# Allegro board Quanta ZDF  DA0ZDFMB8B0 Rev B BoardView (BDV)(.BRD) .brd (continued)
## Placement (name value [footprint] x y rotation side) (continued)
R1108  *4.7K_5%_2  [R0201]  87.92 27.16 90 top
R1109  *4.7K_5%_2  [R0201]  78.11 36.92 0 top
R1110  *4.7K_5%_2  [R0201]  78.11 36.16 0 top
R1111  *4.7K_5%_2  [R0201]  91.25 26.78 0 top
R1112  *4.7K_5%_2  [R0201]  91.25 26.04 0 top
R1113  *4.7K_5%_2  [R0201]  95.2 36.92 180 top
R1114  *4.7K_5%_2  [R0201]  95.2 37.63 180 top
R1501  75K_1%_2  [R0201]  81.03 25.9 90 top
R1502  75K_1%_2  [R0201]  119.19 47.66 90 top
R2001  1_1%_2  [R0201]  105 33.21 90 top
R2204  200K_1%_2  [R0201]  111.29 41.47 180 bottom
R2205  12K_5%_2  [R0201]  106.41 30.33 90 top
R2206  12K_5%_2  [R0201]  105.01 30.18 270 top
R2301  *24K_1%_4  [R0402]  113.04 42.3 0 bottom
R2302  *330K_1%_4  [R0402]  113.5 43.98 0 bottom
R2303  39K_1%_4  [R0402]  111.67 44.11 180 bottom
R2304  *7.5K_1%_2  [R0201]  112.66 43.14 180 bottom
R3001  0_5%_2  [R0201]  52.35 15.04 180 bottom
R3002  *0_5%_2  [R0201]  52.69 14.19 270 bottom
R3003  0_5%_2  [R0201]  51.19 14.19 90 bottom
R3004  *0_5%_2  [R0201]  51.49 12.95 270 bottom
R3005  0_5%_2  [R0201]  52.21 12.95 270 bottom
R3006  *0_5%_2  [R0201]  51.95 14.19 270 bottom
R4001  60.4_1%_2  [R0201]  78.19 44.29 0 top
R4404  240_1%_4  [R0402]  80.53 59.14 270 top
R4405  240_1%_4  [R0402]  81.54 59.14 270 top
R4407  *240_1%_4  [R0402]  82.56 59.14 270 top
R6206  *470_1%_2  [R0201]  106.18 27.13 180 top
R6207  *470_1%_2  [R0201]  107.29 27.13 0 top
R6209  *1K_1%_4  [R0402]  103.33 28.36 0 bottom
R6210  *1.5K_1%_4  [R0402]  104.7 28.49 270 bottom
R6225  *0_5%_4  [R0402]  103.49 26.37 0 bottom
R7701  *Short_0201  [S0201]  142.35 30.23 270 top
R8001  *Short_0201  [S0201]  114.18 35.52 0 top
R8201  1.5K_1%_2  [R0201]  114.05 40.2 0 top
R9499  2.2K_1%_2  [R0201]  54.47 7.5 90 top
R9572  1K_1%_2  [R0201]  141.46 28.96 0 bottom
R90154  4.7K_1%_4  [R0402]  24.62 16.39 0 bottom
R90155  4.7K_1%_4  [R0402]  26.4 16.39 180 bottom
R90163  *Short_0402  [S0402]  107.44 56.4 90 bottom
R90164  *Short_0603  [S0603]  114.2 50.13 180 top
R90264  *Short_0201  [S0201]  142.22 32.52 180 top
R90265  *  [R0402]  34.4 8.24 90 top
R90266  0_5%_4  [R0402]  34.65 9.77 0 top
R90267  2K_1%_4  [R0402]  27.29 4.12 0 top
R90268  69.8K_1%_4  [R0402]  34.65 10.91 0 top
R90332  2.2K_1%_4  [R0402]  11.92 35.69 270 top
R90333  0_5%_4  [R0402]  9.63 35.69 270 top
R90334  0_5%_4  [R0402]  13.98 33.89 90 top
R90335  0_5%_4  [R0402]  6.92 31.38 0 top
R90336  0_5%_2  [R0201]  77.32 32.07 180 top
R90337  0_5%_2  [R0201]  78.47 31.25 180 top
R90338  0_5%_2  [R0201]  77.61 29.22 180 top
R90339  0_5%_2  [R0201]  126.35 45.47 90 top
R90340  *0_5%_2  [R0201]  92.72 26.89 0 top
R90341  *0_5%_2  [R0201]  92.74 29.09 270 top
R90342  *0_5%_2  [R0201]  90.53 30.87 270 top
R90343  *0_5%_2  [R0201]  91.8 29.22 0 top
R90348  *Short_0402  [S0402]  128.13 14.99 270 top
R90352  *Short_0402  [S0402]  31.1 30.11 0 top
R90354  *Short_0402  [S0402]  33.64 30.11 180 top
R90364  *Short_0603  [S0603]  52.31 23.25 0 top
R90365  0_5%_6  [R0603]  54.08 11.69 180 top
R90366  *Short_0603  [S0603]  119.95 52.05 90 top
R90367  0_5%_6  [R0603]  131.55 53.12 270 top
R90368  *Short_0201  [S0201]  122.03 46.64 0 top
R90371  *Short_0201  [S0201]  130.41 52.33 90 top
R90373  *Short_0201  [S0201]  130.28 47.07 180 top
R90374  30.9K_1%_4  [R0402]  58.78 13.06 90 top
R90375  100K_1%_4  [R0402]  50.73 21.47 0 top
R90376  100K_1%_4  [R0402]  123.3 45.47 90 top
R90377  100K_1%_4  [R0402]  51.04 15.5 180 top
R90380  100K_1%_4  [R0402]  52.81 13.34 180 top
R90382  0_5%_2  [R0201]  55.61 13.47 0 bottom
R90383  0_5%_2  [R0201]  55.61 12.71 0 bottom
R90384  0_5%_2  [R0201]  56.37 13.34 90 top
R90385  0_5%_2  [R0201]  55.61 13.34 90 top
R90386  *10K_1%_2  [R0201]  59.85 9.02 270 top
R90387  *10K_1%_2  [R0201]  58.78 9.01 270 top
R90388  470_1%_2  [R0201]  52.97 21.47 270 top
R90389  *Short_0201  [S0201]  52.1 21.34 0 top
R90407  10K_1%_4  [R0402]  59.93 19.06 0 top
R90409  1M_1%_4  [R0402]  60 21.29 180 top
R90410  4.7K_1%_4  [R0402]  54.49 22.43 0 top
R90415  1M_1%_4  [R0402]  56.42 21.47 180 top
R90416  *0_5%_2  [R0201]  145.91 35.44 270 top
R90417  *0_5%_2  [R0201]  145.14 35.44 270 top
R90418  *0_5%_2  [R0201]  146.79 31.63 270 top
R90423  100K_1%_4  [R0402]  61.63 19.87 270 top
R90424  0_5%_2  [R0201]  46.72 23.12 270 top
R90425  0_5%_2  [R0201]  48.14 23.12 270 top
R90426  0_5%_2  [R0201]  46.08 13.6 0 top
R90427  0_5%_2  [R0201]  44.81 13.6 0 top
R90428  0_5%_2  [R0201]  48.88 23.12 270 top
R90429  49.9_1%_2  [R0201]  47.43 23.12 270 top
R90430  49.9_1%_2  [R0201]  44.81 14.36 0 top
R90431  49.9_1%_2  [R0201]  46.08 14.36 0 top
R90432  1K_1%_2  [R0201]  53.2 17.66 0 bottom
R90433  47K_1%_2  [R0201]  53.2 19.18 180 bottom
R90434  *1M_1%_4  [R0402]  58.15 21.47 0 top
R90435  *Short_0201  [S0201]  114.18 34.71 0 top
R90438  *Short_0402  [S0402]  42.81 3.56 270 top
R90439  *Short_0402  [S0402]  42.53 11.82 270 bottom
R90440  *Short_0402  [S0402]  41.38 12.71 270 bottom
R90441  470_1%_2  [R0201]  59.5 15.14 0 top
R90442  *Short_0201  [S0201]  59.5 14.33 180 top
R90448  10K_1%_4  [R0402]  59.93 16.11 180 top
R90449  1K_1%_2  [R0201]  59.57 17.96 0 top
R90450  10K_1%_4  [R0402]  37.35 5.64 90 top
R90451  1M_1%_4  [R0402]  39.23 7.12 90 top
R90452  0_5%_2  [R0201]  57.89 13.34 90 top
R90453  *1K_1%_4  [R0402]  100.97 47.46 180 top
R90455  100K_1%_4  [R0402]  51.04 14.48 180 top
R90457  100K_1%_4  [R0402]  51.04 17.28 180 top
R90460  *100K_1%_4  [R0402]  129.01 53.73 0 top
R90461  *100K_1%_4  [R0402]  77.27 32.91 0 top
R90462  *100K_1%_4  [R0402]  76.66 35.3 0 top
R90463  100K_1%_4  [R0402]  82.38 32.5 270 bottom
R90465  *Short_0201  [S0201]  115.17 57.14 180 top
R90471  *100K_1%_4  [R0402]  95.92 41.06 0 top
R90472  51.1K_1%_4  [R0402]  129.65 50.93 180 top
R90473  30K_1%_4  [R0402]  129.65 48.44 0 top
R90474  *Short_0402  [S0402]  132.19 20.71 270 top
R90475  *Short_0603  [S0603]  45.07 33.46 180 bottom
R90479  *Short_0402  [S0402]  133.21 15.5 270 top
R90481  4.7K_1%_4  [R0402]  37.96 13.54 90 bottom
R90482  4.7K_1%_4  [R0402]  38.34 5.34 270 top
R90483  *4.7K_1%_4  [R0402]  39.84 11.41 180 bottom
R90484  *4.7K_1%_4  [R0402]  41.64 4.32 270 top
R90488  *0_5%_2  [R0201]  43.42 25.03 180 top
R90489  *0_5%_2  [R0201]  43.42 25.79 180 top
R90490  *0_5%_2  [R0201]  43.98 29.9 270 top
R90491  *0_5%_2  [R0201]  43.21 29.9 270 top
R90492  *0_5%_2  [R0201]  13.06 21.39 270 top
R90493  *0_5%_2  [R0201]  12.3 21.39 270 top
R90494  *0_5%_2  [R0201]  9.76 13.9 90 top
R90495  *0_5%_2  [R0201]  10.52 13.9 90 top
R90496  *0_5%_2  [R0201]  13.06 12.5 90 top
R90497  *0_5%_2  [R0201]  12.3 12.5 90 top
R90498  *0_5%_2  [R0201]  117.71 12.96 90 top
R90499  *0_5%_2  [R0201]  118.47 12.96 90 top
R90500  *0_5%_2  [R0201]  119.59 12.2 0 top
R90501  *0_5%_2  [R0201]  119.59 11.44 0 top
R90502  *0_5%_2  [R0201]  125.71 15.75 180 top
R90503  *0_5%_2  [R0201]  125.71 14.99 180 top
R90504  0_5%_2  [R0201]  137.68 59.62 90 top
R90505  47_5%_2  [R0201]  136.97 59.62 90 top
R90506  47_5%_2  [R0201]  136.2 59.62 270 top
R90507  47_5%_2  [R0201]  135.44 59.62 270 top
R90508  47_5%_2  [R0201]  134.55 59.49 0 top
R90509  47_5%_2  [R0201]  134.48 57.87 270 top
R90512  *Short_0402  [S0402]  131.43 15.12 270 top
R90514  *4.7K_5%_2  [R0201]  148.32 34.42 270 top
R90515  *4.7K_5%_2  [R0201]  148.32 32.77 270 top
R90518  *Short_0603  [S0603]  45.83 40.27 90 top
R90519  *Short_0402  [S0402]  127.74 20.71 270 top
R90520  *Short_0201  [S0201]  129.78 15.25 90 top
R90521  2.2K_1%_4  [R0402]  128.28 46.23 270 top
R90522  2.2K_1%_4  [R0402]  127.19 46.23 270 top
R90523  2.2K_1%_4  [R0402]  121.65 49.61 180 top
R90524  2.2K_1%_4  [R0402]  121.65 50.63 180 top
R90525  *Short_0201  [S0201]  124.19 45.47 90 top
R90527  0_5%_2  [R0201]  14.38 29.83 180 top
R90528  0_5%_2  [R0201]  14.38 30.54 180 top
R90529  0_5%_2  [R0201]  8.75 34.3 0 top
R90530  *Short_0402  [S0402]  35.37 8.24 90 top
R90535  *0_5%_2  [R0201]  141.46 30.11 0 top
R90537  *Short_0201  [S0201]  130.54 15.25 90 top
R90538  *Short_0603  [S0603]  21.57 47 180 top
R90539  *0_5%_2  [R0201]  50 39.22 90 top
R90540  *0_5%_2  [R0201]  49.23 39.22 90 top
R90541  *0_5%_2  [R0201]  50.3 36.1 90 top
R90542  *0_5%_2  [R0201]  51.06 36.1 90 top
R90543  *0_5%_2  [R0201]  56.98 43.74 270 top
R90544  *0_5%_2  [R0201]  56.22 43.74 270 top
R90554  *Short_0201  [S0201]  129.4 49.28 0 top
R90558  *Short_0603  [S0603]  101.13 49.42 90 top
R90560  10K_1%_4  [R0402]  97.21 42.91 270 top
R90561  *100K_1%_4  [R0402]  95.89 36.03 0 top
R90562  0_5%_4  [R0402]  99.83 30.57 270 bottom
R90563  *0_5%_4  [R0402]  102.98 30.57 270 bottom
R90568  *0_5%_2  [R0201]  143.49 35.95 0 top
R90569  *0_5%_2  [R0201]  143.49 35.19 0 top
R90580  100K_1%_2  [R0201]  24.11 29.62 0 top
R90581  *1K_1%_4  [R0402]  104.07 30.26 270 top
R90582  *0_5%_2  [R0201]  104.66 27.65 180 top
R90587  *0_5%_2  [R0201]  41 7.5 90 top
R90591  *0_5%_2  [R0201]  87.84 28.08 180 top
R90597  10K_1%_2  [R0201]  111.29 42.3 180 bottom
R90603  *Short_0201  [S0201]  25.48 42.17 90 top
R90604  *Short_0201  [S0201]  24.72 42.17 90 top
R90605  *100K_1%_4  [R0402]  123.68 57.92 90 top
R90606  *Short_0402  [S0402]  105.11 31.55 90 top
R90610  100K_1%_4  [R0402]  44.56 23.37 270 top
R90611  100K_1%_4  [R0402]  45.55 24.77 270 top
R90612  *TS@0_5%_2  [R0201]  44.61 47.86 270 top
R90614  *TS@0_5%_2  [R0201]  43.77 47.86 270 top
R90622  *Short_0201  [S0201]  93.25 34.63 0 bottom
R90624  100K_1%_4  [R0402]  138.76 63.92 90 top
R90625  *100K_1%_4  [R0402]  78.57 41.62 0 top
R90626  *100K_1%_4  [R0402]  78.57 42.58 0 top
R90627  100K_1%_4  [R0402]  137.75 63.92 90 top
R90628  *Short_0201  [S0201]  123.99 53.73 90 top
R90629  10K_1%_4  [R0402]  62.64 19.87 270 top
R90630  100K_1%_4  [R0402]  51.04 13.34 0 top
R90633  *Short_0201  [S0201]  26.98 42.77 90 top
R90638  *Short_0402  [S0402]  77.31 59.43 0 top
R90639  *Short_0402  [S0402]  30.62 33.53 90 top
R90640  *10K_1%_4  [R0402]  49.74 23.48 270 top
R90641  *Short_0402  [S0402]  97.65 37 180 top
R90642  *Short_0402  [S0402]  97.65 39.03 180 top
R90643  *Short_0402  [S0402]  102.32 48.2 90 top
R90644  *Short_0402  [S0402]  103.34 48.2 90 top
R90645  *Short_0402  [S0402]  99.5 34.99 180 top
R90646  *Short_0402  [S0402]  106.36 32.25 270 top
R90647  *Short_0402  [S0402]  112.58 48.77 0 top
R90648  *Short_0402  [S0402]  97.65 41.06 180 top
R90649  *Short_0603  [S0603]  104.66 48.86 90 top
R90650  *Short_0402  [S0402]  114.56 36.56 180 top
R90651  *Short_0402  [S0402]  112.56 38.57 90 top
R90652  *Short_0402  [S0402]  113.16 47.41 90 top
R90653  *Short_0402  [S0402]  99.96 31.64 90 top
R90654  *Short_0402  [S0402]  112.2 42.13 0 top
R90655  *Short_0402  [S0402]  112.2 47.41 90 top
R90656  *0_5%_2  [R0201]  112.58 36.16 90 bottom
R90658  *Short_0201  [S0201]  108.16 29.52 0 top
R90659  *Short_0201  [S0201]  107.48 34.53 0 top
R90662  *Short_0603  [S0603]  58.43 19.69 90 bottom
R90666  1K_1%_2  [R0201]  63.74 18.7 0 bottom
R90667  *Short_0402  [S0402]  64.37 20.58 180 bottom
R90668  *Short_0603  [S0603]  76.23 18.47 180 bottom
R90669  *Short_0402  [S0402]  98.51 20.86 0 bottom
R90671  16.5K_1%_2  [R0201]  92.31 17.66 180 bottom
R90672  *Short_0603  [S0603]  87.59 18.17 90 bottom
R90673  12.1K_1%_2  [R0201]  91.17 17.66 180 bottom
R90674  *Short_0603  [S0603]  42.99 31.1 180 bottom
R90675  *Short_0402  [S0402]  49.89 32.95 0 bottom
R90677  1K_1%_2  [R0201]  52.34 32.34 90 bottom
R90678  *Short_0603  [S0603]  57.13 34.5 270 bottom
R90680  *Short_0201  [S0201]  52.59 16.64 180 bottom
R90681  *Short_0201  [S0201]  51.42 16.39 180 top
R90682  *Short_0402  [S0402]  46.24 13.26 180 bottom
R90683  *0_5%_2  [R0201]  40.88 6.61 0 top
R90688  *Short_0201  [S0201]  127.69 53.73 90 top
R90692  *100K_1%_4  [R0402]  113.36 57.67 270 top
R90695  *Short_0201  [S0201]  53.32 9.79 270 bottom
R90696  0_5%_2  [R0201]  92.72 26.17 0 top
R90697  0_5%_2  [R0201]  93.45 29.09 270 top
R90698  0_5%_2  [R0201]  91.68 28.33 270 top
R90699  0_5%_2  [R0201]  90.51 29.98 0 top
R90700  0_5%_2  [R0201]  91.92 30.36 270 top
R90701  0_5%_2  [R0201]  88.83 28.07 0 top
R90706  *  [R0402]  20.28 5.44 0 top
R90707  0_5%_4  [R0402]  22.11 5.44 0 top
R90708  *Short_0402  [S0402]  19.46 4.32 180 top
R90715  *0_5%_2  [R0201]  131.02 56.39 270 bottom
R90716  *0_5%_2  [R0201]  130.21 56.39 270 bottom
R90717  *0_5%_2  [R0201]  121.37 59.47 180 bottom
R90718  *0_5%_2  [R0201]  121.37 60.18 180 bottom
R90719  *0_5%_2  [R0201]  116.7 30.94 180 bottom
R90720  *0_5%_2  [R0201]  116.7 31.65 180 bottom
R90725  51.1K_1%_4  [R0402]  87.51 26.17 180 top
R90726  2.2K_1%_4  [R0402]  85.58 26.24 0 top
R90727  51.1K_1%_4  [R0402]  87.51 25.21 180 top
R90728  150K_1%_4  [R0402]  85.58 25.28 0 top
R90729  *51.1K_1%_4  [R0402]  89.42 26.17 0 top
R90732  200K_1%_4  [R0402]  89.42 25.18 0 top
R90735  *Short_0402  [S0402]  25.56 15.09 180 top
R90737  *0_5%_4  [R0402]  13.95 23.25 0 top
R90738  *2.2K_1%_4  [R0402]  103.36 27.37 180 bottom
R90740  698_1%_4  [R0402]  120.9 33.57 180 top
R90741  619_1%_4  [R0402]  65.24 22.36 90 top
R90742  0_5%_2  [R0201]  9.07 54.02 270 bottom
R90743  0_5%_2  [R0201]  9.07 55.01 90 bottom
R90744  0_5%_2  [R0201]  10.65 51.06 90 bottom
R90745  0_5%_2  [R0201]  11.41 51.06 90 bottom
R90746  1M_1%_4  [R0402]  67.32 23.78 0 top
R90751  *100K_1%_2  [R0201]  48.14 11.18 180 top
R90753  *100K_1%_2  [R0201]  50.4 9.15 270 top
R90757  *0_5%_2  [R0201]  99.96 34 90 top
R90758  *Short_0201  [S0201]  94.37 36.2 0 top
R90759  *0_5%_4  [R0402]  13.95 25.53 180 top
R90760  *0_5%_4  [R0402]  6.92 29.22 0 top
R90761  *0_5%_4  [R0402]  8.49 26.04 0 top
R90762  *0_5%_4  [R0402]  6.92 28.2 0 top
R90763  *0_5%_4  [R0402]  8.62 35.69 270 top
R90764  *0_5%_4  [R0402]  13.95 24.52 180 top
R90765  0_5%_4  [R0402]  6.71 26.68 90 top
R90773  *0_5%_4  [R0402]  106.13 25.92 90 top
R90774  *0_5%_4  [R0402]  107.1 25.92 90 top
R90776  *0_5%_4  [R0402]  8.49 24.01 180 top
R90777  *0_5%_4  [R0402]  15.86 27.18 0 top
R90778  0_5%_4  [R0402]  14.08 27.18 180 top
R90779  0_5%_4  [R0402]  7.09 35.19 180 top
R90780  *0_5%_4  [R0402]  7.09 36.2 180 top
R90781  *0_5%_4  [R0402]  8.49 25.03 180 top
R90782  *0_5%_4  [R0402]  10.12 22.1 0 top
R90783  *Short_0201  [S0201]  24.57 19.51 180 bottom
R90784  *Short_0201  [S0201]  26.7 19.18 0 bottom
R90792  0_5%_2  [R0201]  65.01 21.6 270 bottom
R90810  2M_1%_2  [R0201]  10.52 51.92 180 bottom
R90811  2M_1%_2  [R0201]  11.54 51.92 0 bottom
R90813  22_1%_2  [R0201]  27.54 28.58 270 top
R90814  22_1%_2  [R0201]  28.3 28.58 270 top
R90815  *Short_0201  [S0201]  39.48 37.98 270 top
R90816  22_1%_2  [R0201]  26.02 28.58 270 top
R90818  22_1%_2  [R0201]  26.78 28.58 270 top
R90819  *Short_0603  [S0603]  89.21 12.15 90 bottom
R90820  22_1%_2  [R0201]  38.9 20.38 180 bottom
R90821  22_1%_2  [R0201]  37.6 19.59 180 bottom
R90822  22_1%_2  [R0201]  37.7 20.33 180 bottom
R90823  22_1%_2  [R0201]  37.6 18.14 180 bottom
R90824  22_1%_2  [R0201]  39.81 18.52 90 bottom
R90825  22_1%_2  [R0201]  37.6 18.88 180 bottom
R90826  22_1%_2  [R0201]  38.72 18.6 180 bottom
R90827  22_1%_2  [R0201]  37.12 16.31 180 bottom
R90828  22_1%_2  [R0201]  39.99 16.52 180 bottom
R90829  22_1%_2  [R0201]  38.92 17.2 180 bottom
R90830  22_1%_2  [R0201]  37.63 17.43 180 bottom
R90831  22_1%_2  [R0201]  37.73 21.14 180 bottom
R90832  22_1%_2  [R0201]  38.84 21.16 180 bottom
R90833  22_1%_2  [R0201]  38.82 21.88 180 bottom
R90834  22_1%_2  [R0201]  38.82 22.64 180 bottom
R90835  10_5%_12  [R1206]  130.13 37.95 0 top
R90836  1_5%_2  [R0201]  37.32 45.73 0 top
R90837  1_5%_2  [R0201]  37.32 46.49 0 top
R90838  *4.7_5%_12  [R1206]  138.29 37.75 180 bottom
R90839  *4.7_5%_12  [R1206]  139.81 22.99 180 bottom
R90840  1_5%_2  [R0201]  102.6 16.16 90 bottom
R90841  1_5%_2  [R0201]  101.74 16.16 90 bottom
R90842  100_1%_2  [R0201]  121.37 29.32 0 top
R90843  10K_1%_2  [R0201]  134.86 49.79 0 top
R90844  *Short_0201  [S0201]  143.42 47.07 90 top
R90845  *Short_0201  [S0201]  133.16 47.68 90 bottom
R90852  *Short_0402  [S0402]  146.26 18.24 90 top
R90853  10K_1%_4  [R0402]  141.59 21.22 270 top
R90854  10K_1%_4  [R0402]  142.58 21.22 270 top
R90855  *0_5%_4  [R0402]  143.92 20.83 180 top
R90856  *ECO@0_5%_2  [R0201]  147.68 40.39 90 top
R90857  *ECO@0_5%_2  [R0201]  148.5 40.39 90 top
R90858  *0_5%_2  [R0201]  132.85 9.91 270 top
R90859  0_5%_2  [R0201]  124.01 9.91 270 top
R90860  *ECO@0_5%_2  [R0201]  150.43 40.49 180 top
R90861  10K_1%_4  [R0402]  5.19 24.14 0 top
R90868  *Short_0201  [S0201]  129.14 46.59 90 top
R90870  100K_1%_2  [R0201]  15.55 26.5 0 bottom
R90871  **ECO@4.7K_5%_2  [R0201]  147.68 39.38 270 top
R90872  **ECO@4.7K_5%_2  [R0201]  148.5 39.38 270 top
R90874  *Short_0402  [S0402]  38.54 3.94 180 top
R90876  *Short_0201  [S0201]  104.63 41.24 180 bottom
R90877  *Short_0402  [S0402]  95.13 31.84 90 top
R90892  *Short_0201  [S0201]  126.35 46.62 90 top
R90893  *Short_0201  [S0201]  126.17 53.73 90 top
R90897  10K_1%_2  [R0201]  133.48 64.27 180 top
R90898  1M_1%_4  [R0402]  133.48 63.03 90 top
R90899  10K_1%_2  [R0201]  133.92 47.68 270 bottom
R90900  10K_1%_2  [R0201]  133.48 65.01 0 top
R90901  1M_1%_4  [R0402]  136.73 63.92 90 top
R90904  *Short_0201  [S0201]  108.64 39.64 180 bottom
R90906  1M_1%_4  [R0402]  125.2 46.23 270 top
R90912  *Short_0402  [S0402]  48.37 16.52 0 bottom
R90913  *10K_1%_4  [R0402]  50.91 16.52 180 bottom
R90914  *Short_0402  [S0402]  26.58 8.08 270 top
R90915  *Short_0402  [S0402]  29.75 7.7 0 top
R90916  *Short_0402  [S0402]  23.22 6.86 0 top
R90917  *Short_0402  [S0402]  24.95 8.03 270 top
R90937  100K_1%_2  [R0201]  53.58 16.64 0 bottom
R90941  *Short_0201  [S0201]  33.51 33.92 180 top
R90952  10K_1%_2  [R0201]  42.48 41.31 270 top
R90953  10K_1%_2  [R0201]  43.24 41.31 270 top
R90962  *0_5%_4  [R0402]  45.45 4.32 270 top
R90963  *0_5%_4  [R0402]  44.43 4.32 270 top
R90966  *Short_0201  [S0201]  47.99 18.17 0 bottom
R90967  *Short_0201  [S0201]  47.99 18.93 0 bottom
R90969  *Short_0201  [S0201]  49.64 16.52 270 bottom
R90973  4.7K_1%_4  [R0402]  58.15 22.49 0 top
R90974  *1M_1%_4  [R0402]  54.19 21.47 0 top
R90975  *1M_1%_4  [R0402]  59.98 22.28 0 top
R90976  *4.7K_1%_4  [R0402]  56.42 22.49 0 top
R90982  *57.6K_1%_4  [R0402]  122.72 54.67 180 top
R90983  *18K_1%_4  [R0402]  122.74 53.7 0 top
R90984  *Short_0201  [S0201]  62.11 15.37 270 top
R90985  *Short_0402  [S0402]  59.75 13.04 90 top
R90986  *0_5%_4  [R0402]  40.75 12.45 180 top
R90987  *100K_1%_2  [R0201]  41.26 9.15 90 top
R90988  *0_5%_4  [R0402]  37.32 12.66 0 top
R90991  *0_5%_2  [R0201]  46.97 9.66 180 top
R90992  *0_5%_4  [R0402]  48.75 12.07 0 top
R90993  *0_5%_4  [R0402]  42.27 12.96 270 top
R90995  *0_5%_2  [R0201]  145.02 36.33 0 top
R91008  47K_1%_2  [R0201]  112.83 55.64 90 top
R91009  47K_1%_2  [R0201]  112.83 54.57 90 top
R91013  0_5%_2  [R0201]  37.68 21.88 180 bottom
R91028  *1M_1%_4  [R0402]  29.83 45.73 180 top
R91029  *0_5%_2  [R0201]  31.22 45.6 0 top
R91031  *Short_0201  [S0201]  114.23 57.29 270 top
R91032  0_5%_2  [R0201]  25.13 28.58 270 top
R91051  2.2K_1%_2  [R0201]  142.6 22.54 0 top
R91052  2.2K_1%_2  [R0201]  142.48 25.79 0 top
R91057  523_1%_4  [R0402]  30.06 38.39 90 bottom
R91061  0_5%_2  [R0201]  18.14 43.19 180 top
R91062  0_5%_2  [R0201]  18.14 44.08 180 top
R91063  2.2K_1%_2  [R0201]  27.64 38.74 270 bottom
R91064  100K_1%_2  [R0201]  28.41 38.74 270 bottom
R91066  10K_1%_2  [R0201]  134.55 58.73 180 top
R91079  0_5%_2  [R0201]  59.42 23.27 270 top
R91080  0_5%_2  [R0201]  79.66 30.23 270 top
R91081  0_5%_2  [R0201]  76.69 30.36 270 top
R91082  0_5%_2  [R0201]  77.61 28.5 180 top
R91087  *100K_1%_2  [R0201]  60.61 8 90 top
R91088  *0_5%_2  [R0201]  56.5 3.69 270 top
R91089  *100K_1%_2  [R0201]  58.06 8.01 90 top
R91091  *0_5%_4  [R0402]  101.86 30.57 90 bottom
R91092  *1M_1%_4  [R0402]  61.83 8.01 0 top
R91093  *1M_1%_4  [R0402]  56.83 7.7 180 top
R91094  *ALS@0_5%_2  [R0201]  150.88 36.96 270 top
R91097  100K_1%_2  [R0201]  71.46 31.25 180 top
R91098  10K_1%_2  [R0201]  72.55 30.79 0 top
R91099  10K_1%_2  [R0201]  72.65 26.78 180 top
R91100  *Short_0402  [S0402]  62.77 31.76 180 top
R91111  *Short_0201  [S0201]  41.56 41.54 90 top
R91112  2.2K_1%_2  [R0201]  54.47 6.1 90 top
R91113  100K_1%_2  [R0201]  53.07 4.83 180 top
R91115  0_5%_2  [R0201]  58.06 9.01 270 top
R91116  0_5%_2  [R0201]  54.8 13.34 270 top
R91117  *Short_0201  [S0201]  23.48 42.55 180 top
R91118  *Short_0201  [S0201]  23.48 43.29 180 top
R91121  0_5%_2  [R0201]  126.14 9.91 270 top
R91125  *Short_0402  [S0402]  42.78 33.92 0 bottom
R91126  TS@1.5K_1%_2  [R0201]  43.77 46.74 90 top
R91127  TS@1.5K_1%_2  [R0201]  44.61 46.74 90 top
R91129  TS@10K_1%_2  [R0201]  51.75 47.38 270 top
R91130  *TS@10K_1%_2  [R0201]  48.75 48.14 90 top
R91131  *TS@10K_1%_2  [R0201]  52.69 47.63 90 top
R91132  TS@100K_1%_2  [R0201]  55.99 47.3 0 top
R91133  *TS@0_5%_4  [R0402]  56.24 48.19 180 top
R91134  10K_1%_2  [R0201]  133.54 49.33 180 bottom
R91135  *TS@0_5%_4  [R0402]  47.86 47.89 90 top
R91136  *Short_0603  [S0603]  131.83 57.88 270 top
R91137  10K_1%_2  [R0201]  140.52 60.76 180 top
R91139  *Short_0603  [S0603]  118.67 60.49 180 bottom
R91140  0_5%_4  [R0402]  6.92 30.36 0 top
R91141  *0_5%_2  [R0201]  133.54 48.57 180 bottom
R91142  10K_1%_2  [R0201]  124.19 46.62 90 top
R91143  *0_5%_2  [R0201]  141.84 10.93 0 top
R91144  *ECO@0_5%_2  [R0201]  149.72 47.45 270 top
R91145  *10K_1%_4  [R0402]  136.94 11.74 180 top
R91146  *ECO@0_5%_2  [R0201]  146.67 40.39 90 top
R91147  *Short_0201  [S0201]  54.08 13.34 270 top
R91148  *1M_1%_4  [R0402]  102.8 17.58 90 bottom
R91150  22_1%_2  [R0201]  38.84 19.31 180 bottom
R91151  22_1%_2  [R0201]  29.07 28.58 270 top
R91152  22_1%_2  [R0201]  25.13 29.85 270 top
R91156  220K_1%_2  [R0201]  18.52 39.63 270 top
R91157  220K_1%_2  [R0201]  19.29 39.63 270 top
R91158  220K_1%_2  [R0201]  23.22 38.23 270 top
R91159  220K_1%_2  [R0201]  23.99 38.23 270 top
R91160  *Short_0201  [S0201]  51.42 18.17 180 top
R91161  619_1%_4  [R0402]  135.24 17.28 180 top
R91162  150_1%_4  [R0402]  135.24 16.26 180 top
R91163  150_1%_4  [R0402]  135.24 15.25 180 top
R91169  10K_1%_2  [R0201]  91.17 16.9 0 bottom
R91170  *0_5%_2  [R0201]  15.71 14.2 0 top
R91171  *0_5%_2  [R0201]  32.24 45.6 180 top
R91172  *Short_0201  [S0201]  29.17 38.74 270 bottom
R91173  *Short_0201  [S0201]  123.93 54.74 90 top
R91174  *Short_0201  [S0201]  124.85 53.7 90 top
R91175  *Short_0201  [S0201]  126.93 53.73 90 top
R91179  *Short_0201  [S0201]  122.18 51.67 270 top
R91181  *Short_0402  [S0402]  37.45 11.82 270 bottom
R91182  499K_1%_4  [R0402]  119.36 38.36 90 top
R91183  10K_1%_2  [R0201]  119.38 37.14 0 top
R91184  *100K_1%_2  [R0201]  119.37 36.41 0 top
R91185  100K_1%_2  [R0201]  65.01 22.61 90 bottom
R91186  100K_1%_4  [R0402]  51.04 19.06 0 top
R91187  *Short_0201  [S0201]  120.3 48.88 90 top
R91188  *0_5%_2  [R0201]  59.85 8 270 top
R91189  *0_5%_2  [R0201]  58.78 8 270 top
R91190  *100K_1%_2  [R0201]  146.29 37.85 90 top
R91191  100_1%_2  [R0201]  122.7 36.07 270 top
R91192  100K_1%_2  [R0201]  121.77 37.28 270 top
R91194  *Short_0201  [S0201]  121.01 27.69 270 top
R91195  *Short_0201  [S0201]  121.14 32.59 270 top
R91196  *100K_1%_2  [R0201]  122.16 47.63 90 top
R91199  100K_1%_2  [R0201]  41.49 36.38 0 top
R91200  *Short_0603  [S0603]  104.02 17.1 270 bottom
R91202  0_5%_2  [R0201]  138.41 21.09 180 top
R91203  0_5%_2  [R0201]  139.56 21.09 0 top
R91204  *0_5%_2  [R0201]  138.41 20.33 180 top
R91205  *0_5%_2  [R0201]  139.56 20.33 0 top
R91206  *0_5%_2  [R0201]  89.57 31.58 0 top
R91207  0_5%_4  [R0402]  20.53 11.92 270 top
R91209  *Short_0201  [S0201]  123.17 46.74 0 top
R91210  2.2K_1%_2  [R0201]  140.57 22.26 180 top
R91211  2.2K_1%_2  [R0201]  140.32 25.79 180 top
R91212  100K_1%_2  [R0201]  51.67 4.83 180 top
R91213  *0_5%_2  [R0201]  135.24 13.6 180 top
R91214  *0_5%_2  [R0201]  135.24 12.83 180 top
R91217  0_5%_2  [R0201]  77.22 34.46 180 top
R91218  0_5%_2  [R0201]  77.22 33.75 180 top
R91219  *0_5%_2  [R0201]  147.56 32.77 90 top
R91220  *0_5%_2  [R0201]  147.56 33.92 270 top
R91221  *0_5%_2  [R0201]  146.79 33.92 270 top
R91222  *0_5%_2  [R0201]  146.79 32.77 90 top
R91223  *0_5%_2  [R0201]  147.56 31.63 90 top
R91224  *0_5%_2  [R0201]  144.38 35.44 270 top
R91225  100K_1%_2  [R0201]  138.03 40.16 90 bottom
R91226  1.2K_1%_6  [R0603]  24.62 47.55 270 top
R91228  *Short_0402  [S0402]  68.84 53.42 0 top
R91229  *Short_0402  [S0402]  68.66 50.6 270 top
R91230  *Short_0201  [S0201]  71.31 53.42 180 top
R91231  1M_1%_4  [R0402]  66.66 36.07 270 top
R91232  1M_1%_4  [R0402]  55.02 37.7 270 top
R91233  4.7K_5%_2  [R0201]  55.99 40.14 90 top
R91234  *Short_0402  [S0402]  70.85 49.05 270 top
R91235  *Short_0402  [S0402]  69.68 49.08 270 top
R91236  *Short_0402  [S0402]  65.29 46.95 180 top
R91237  *Short_0402  [S0402]  67.06 46.95 0 top
R91238  4.7K_5%_2  [R0201]  63.99 46.95 270 top
R91239  1M_1%_4  [R0402]  63.71 38.92 180 top
R91240  2.2K_1%_2  [R0201]  65.03 45.52 90 bottom
R91241  2.2K_1%_2  [R0201]  65.77 45.55 90 bottom
R91242  100K_1%_2  [R0201]  51.65 37.52 90 top
R91243  *GMR@1K_1%_2  [R0201]  127.24 66.94 90 top
R91244  *GMR@1K_1%_2  [R0201]  128 66.94 270 top
R91245  1M_1%_4  [R0402]  28.05 47.89 270 top
R91246  4.7K_5%_2  [R0201]  131.43 55.76 270 top
R91247  4.7K_5%_2  [R0201]  128.13 56.39 270 top
R91248  2.2K_1%_2  [R0201]  128.13 55.38 270 top
R91249  2.2K_1%_2  [R0201]  124.82 56.01 270 top
R91250  *0_5%_4  [R0402]  29.07 47.89 90 top
R91251  0_5%_4  [R0402]  30.08 47.89 270 top
R91252  1K_1%_2  [R0201]  141.46 30.23 0 bottom
R91253  4.7K_5%_2  [R0201]  60.82 44.33 0 top
R91254  *4.7K_5%_2  [R0201]  60.69 38.23 0 top
R91255  *0_5%_2  [R0201]  65.77 46.54 270 bottom
R91256  *0_5%_2  [R0201]  65.03 46.54 270 bottom
R91257  *0_5%_2  [R0201]  62.82 34.96 180 top
R91258  *0_5%_2  [R0201]  66.4 38.92 90 top
R91259  *Short_0201  [S0201]  65.67 38.92 270 top
R91260  *0_5%_4  [R0402]  72.12 49.03 270 top
R91261  *0_5%_4  [R0402]  47.18 44.74 90 top
R91265  *1M_1%_4  [R0402]  62.62 17.89 270 bottom
R91266  *1M_1%_4  [R0402]  46.01 31.83 180 bottom
R91267  1M_1%_4  [R0402]  103.11 12.58 0 top
R91268  *Short_0402  [S0402]  101.2 12.58 180 top
R91269  *1M_1%_4  [R0402]  61.45 22.74 180 bottom
R91270  80.6K_1%_4  [R0402]  61.45 21.72 0 bottom
R91271  0_5%_6  [R0603]  73.52 6.97 180 top
R91273  *0_5%_4  [R0402]  48.55 33.31 270 bottom
R91274  *10K_1%_4  [R0402]  47.58 33.81 90 bottom
R91275  100K_1%_4  [R0402]  49.94 33.92 180 bottom
R91276  0_5%_4  [R0402]  47.58 32.09 90 bottom
R91277  10K_1%_2  [R0201]  42.4 19.82 0 bottom
R91278  1M_1%_4  [R0402]  46.34 19.82 180 bottom
R91279  *499K_1%_4  [R0402]  123.68 56.14 270 top
R91280  *Short_0201  [S0201]  78.47 29.72 270 top
R91281  100K_1%_4  [R0402]  60.82 20.33 90 bottom
R91282  *300K_1%_2  [R0201]  16.29 29.72 270 top
R91283  100K_1%_2  [R0201]  24.49 33.41 180 top
R91284  100K_1%_2  [R0201]  23.48 33.41 0 top
R91285  100K_1%_2  [R0201]  22.46 36.84 180 top
R91286  100K_1%_2  [R0201]  21.45 36.84 0 top
R91287  100K_1%_2  [R0201]  21.57 33.92 180 top
R91288  100K_1%_2  [R0201]  20.56 33.92 0 top
R91289  100K_1%_2  [R0201]  19.67 35.44 180 top
R91290  100K_1%_2  [R0201]  18.65 35.44 0 top
R91291  *Short_0201  [S0201]  16.11 31.25 270 top
R91292  *Short_0201  [S0201]  16.87 31.25 270 top
R91293  22_1%_2  [R0201]  17.25 33.28 270 top
R91294  22_1%_2  [R0201]  16.49 33.28 270 top
R91295  0_5%_6  [R0603]  28.56 37.85 180 top
R91296  *0_5%_2  [R0201]  143.7 22.1 270 top
R91297  *0_5%_2  [R0201]  145.7 26.88 0 top
R91298  4.7K_5%_2  [R0201]  26.98 15.09 180 top
R91299  0_5%_2  [R0201]  113.34 36.16 90 bottom
R91300  *Short_0201  [S0201]  63.46 29.52 0 top
R91301  *Short_0201  [S0201]  63.46 28.81 0 top
R91302  499K_1%_4  [R0402]  122.28 55.73 0 top
R91303  *0_5%_6  [R0603]  56.73 11.69 0 top
R91304  *0_5%_6  [R0603]  132.65 47.91 180 top
R91305  499K_1%_4  [R0402]  47.71 32.57 270 top
R91306  100K_1%_2  [R0201]  72.2 8.39 0 top
R91307  *0_5%_4  [R0402]  51.27 32.57 270 top
R91308  *0_5%_4  [R0402]  50.15 32.57 270 top
R91309  100K_1%_2  [R0201]  52.48 25.96 0 top
R91310  0_5%_4  [R0402]  52.48 31.35 90 top
R91311  *0_5%_2  [R0201]  54.21 14.59 0 bottom
R91312  0_5%_2  [R0201]  52.94 12.96 90 bottom
R91313  *0_5%_2  [R0201]  54.21 13.87 0 bottom
R91314  0_5%_2  [R0201]  58.4 3.56 0 top
R91315  0_5%_2  [R0201]  55.46 8.25 180 top
R91316  *0_5%_2  [R0201]  61.7 9.02 270 top
R91317  0_5%_2  [R0201]  72.88 46.62 270 bottom
R91318  *0_5%_2  [R0201]  73.64 46.62 270 bottom
R91319  0_5%_2  [R0201]  70.47 40.39 270 bottom
R91320  150_5%_4  [R0402]  73.64 45.22 90 bottom
R91321  *22K_1%_4  [R0402]  74.66 41.28 270 bottom
R91322  30K_1%_4  [R0402]  73.64 41.28 270 bottom
R91323  *499K_1%_4  [R0402]  14.51 26.02 270 bottom
R91324  10K_1%_2  [R0201]  68.46 32.09 270 top
R91325  10K_1%_2  [R0201]  72.37 29.47 270 top
R91326  0_5%_4  [R0402]  19.29 41.92 270 bottom
R91327  *0_5%_4  [R0402]  20.68 42.3 0 bottom
R91328  *0_5%_2  [R0201]  25.51 40.75 90 bottom
R91329  *0_5%_2  [R0201]  25.43 43.11 0 bottom
R91330  100K_1%_4  [R0402]  61.45 23.76 180 bottom
R91331  0_5%_2  [R0201]  138.79 40.52 90 bottom
RTC32K_2V8  *TP  [TP2050]  112.3 33.44 270 bottom
SH1701  *SHORT_20MIL  [S0402]  84.31 27.21 180 top
SH1801  *SHORT_4MIL  [SHORT8X4]  89.03 40.17 90 bottom
SH1802  *SHORT_4MIL  [SHORT8X4]  88.73 40.17 270 bottom
SH1803  *SHORT_4MIL  [SHORT8X4]  83.02 34.68 90 bottom
SH1804  *SHORT_4MIL  [SHORT8X4]  82.63 34.68 270 bottom
SH1805  *SHORT_4MIL  [SHORT8X4]  86.6 38.34 90 bottom
SH1806  *SHORT_4MIL  [SHORT8X4]  86.37 38.34 270 bottom
SH1807  *SHORT_4MIL  [SHORT8X4]  82.79 37.5 0 bottom
SH1808  *SHORT_4MIL  [SHORT8X4]  82.79 37.2 180 bottom
SH2001  *SHORT_4MIL  [SHORT8X4]  105.44 34.58 90 top
SH2002  *SHORT_20MIL  [S0402#2]  101.63 37.5 0 bottom
SH2003  *SHORT_20MIL  [S0402#2]  101.63 39.33 0 bottom
SH2006  *SHORT_20MIL  [S0402#2]  104.66 43.24 270 bottom
SH2008  *SHORT_20MIL  [S0402#2]  105.8 45.33 270 bottom
SH2010  *SHORT_20MIL  [S0402#2]  101.66 36.54 0 bottom
SH2011  *SHORT_20MIL  [S0402#2]  103.59 33.51 0 bottom
SH2012  *SHORT_20MIL  [S0402#2]  108.54 44.51 270 bottom
SH2013  *SHORT_20MIL  [S0402#2]  101.61 40.3 0 bottom
SH2015  *SHORT_20MIL  [S0402#2]  106.56 43.39 0 bottom
SH2101  *SHORT_20MIL  [S0402]  97.67 32.98 90 bottom
SH2140  *SHORT_4MIL  [SHORT8X4]  110.52 40.78 90 bottom
SH2144  *SHORT_4MIL  [SHORT8X4]  111.82 35.83 270 bottom
SH2302  *SHORT_4MIL  [SHORT8X4]  109.39 41.52 0 bottom
SH4401  *SHORT_4MIL  [SHORT8X4]  78.14 47.73 270 bottom
SH4402  *SHORT_4MIL  [SHORT8X4]  77.78 47.73 270 bottom
SH6101  *SHORT_4MIL  [SHORT8X4]  109 33.69 90 bottom
SH6102  *SHORT_4MIL  [SHORT8X4]  107.75 32.86 180 top
SH6204  *SHORT_20MIL  [S0402]  10.27 23.25 180 top
SH8101  *SHORT_4MIL  [SHORT8X4]  109.38 34.7 90 top
SH8102  *SHORT_4MIL  [SHORT8X4]  109.15 32.7 270 top
SW7504  *NTC316-AD1T-A160T-A  [SW-NTC316-AD1T-A160T-4P]  4.05 29.32 270 top
TP109  *TP  [TP2050]  127.97 33.61 270 top
TP110  *TP  [TP2050]  121.77 34.57 270 top
TP212  *TP  [TP2050]  17.41 26.14 0 top
TP213  *TP  [TP2050]  17.05 27.51 0 top
TP230  *TP  [TP2050]  18.88 33.03 0 top
TP231  *TP  [TP2050]  16.82 28.78 0 top
TP8273  *TP  [TP2050]  113.19 60.49 270 top
TP8274  *TP  [TP2050]  114.26 59.49 90 top
TP8275  *TP  [TP2050]  95.2 47.92 90 top
TP9044  *TP  [TP2050]  28.68 26.93 270 bottom
TP9055  *TP  [TP2050]  145.02 30.11 0 top
TP9060  *TP  [TP2050]  138.02 63.02 90 bottom
TP9061  *TP  [TP2050]  139.55 63.09 90 bottom
TP9064  *TP  [TP2050]  79.08 43.72 90 top
TP9065  *TP  [TP2050]  90.79 25.18 90 top
TP9066  *TP  [TP2050]  76.94 43.69 90 top
TP9067  *TP  [TP2050]  91.93 24.54 90 top
TP9068  *TP  [TP2050]  87.33 29.01 90 top
TP9069  *TP  [TP2050]  79.25 37.05 90 top
TP9070  *TP  [TP2050]  79.46 31.32 90 top
TP9071  *TP  [TP2050]  78.39 40.2 90 top
TP9072  *TP  [TP2050]  27.59 9.63 180 top
TP9073  *TP  [TP2050]  28.38 8.54 180 top
TP9074  *TP  [TP2050]  22 6.36 180 top
TP9075  *TP  [TP2050]  23.48 8.5 180 top
TP9079  *TP  [TP2050]  76.44 29.34 0 top
TP9080  *TP  [TP2050]  79.61 29.22 90 top
TP9083  *TP  [TP2050]  147.51 47.55 0 top
TP9084  *TP  [TP2050]  148.8 47.55 0 top
TP9141  *TP  [TP2050]  90.66 31.76 0 top
TP9142  *TP  [TP2050]  58.71 9.76 180 bottom
TP9143  *TP  [TP2050]  108.49 33.23 0 top
TP9146  *TP  [TP2050]  135.49 12.07 0 top
TP9149  *TP  [TP2050]  135.36 14.36 0 top
TP9151  *TP  [TP2050]  140.57 20.2 0 top
TP9152  *TP  [TP2050]  140.57 21.47 0 top
TP9154  *TP  [TP2050]  34.27 5.85 180 bottom
TP9155  *TP  [TP2050]  34.27 4.45 180 bottom
TP9157  *TP  [TP2050]  51.57 6.99 180 bottom
TP9158  *TP  [TP2050]  51.67 4.32 180 bottom
TP9159  *TP  [TP2050]  51.67 5.72 180 bottom
TP9160  *TP  [TP2050]  51.98 8.79 180 bottom
TP9161  *TP  [TP2050]  34.48 9 0 bottom
TP9162  *TP  [TP2050]  36 11.21 0 bottom
TP9163  *TP  [TP2050]  36 12.58 0 bottom
TP9165  *TP  [TP2050]  43.7 11.41 0 bottom
TP9166  *TP  [TP2050]  43.7 12.68 0 bottom
TP9167  *TP  [TP2050]  42.55 13.57 0 bottom
TP9168  *TP  [TP2050]  47.43 12.43 0 bottom
TP9169  *TP  [TP2050]  46.8 11.26 0 bottom
TP9170  *TP  [TP2050]  48.88 19.64 180 bottom
TP9175  *TP  [TP2050]  143.87 11.94 0 top
TP9176  *TP  [TP2050]  112.81 26.5 0 top
TP9177  *TP  [TP2050]  66.02 34.5 0 top
TP9178  *TP  [TP2050]  64.7 34.5 0 top
TP9179  *TP  [TP2050]  61.78 40.27 0 top
TP9180  *TP  [TP2050]  76.01 32.9 0 top
TP9181  *TP  [TP2050]  89.64 30.74 0 top
TP9182  *TP  [TP2050]  64.27 39.96 180 bottom
TP9183  *TP  [TP2050]  142.95 37.83 0 top
TP9184  *TP  [TP2050]  26.14 39.76 180 bottom
U1  IT6505FN/BX  [QFN88-10X10-4-89P-FL5001]  28.43 21.72 180 top
U2  AZ1045-04F.R7G  [ESD10-2_5X1-5-9P-AZ1143]  10.19 53.3 270 top
U3  AZ1045-04F.R7G  [ESD10-2_5X1-5-9P-AZ1143]  13.57 52.81 90 top
U5  *SN74AVC16T245ZQLR  [BGA56-TEXAS-SN74AVC16T245]  38.34 19.31 270 top
U6  ISL9238CHRTZ-T  [QFN32-4X4-4-33P-ISL95812HRZ-SMT]  124.7 32.39 0 top
U12  *TLV8802DGKR  [MSOP8-4_9-65]  59.42 5.72 90 top
U18  H26M62002JPR  [BGA153-SANDISK-SDIN7DP4-16G]  104.64 59.61 0 top
U23  RT5710AHGQW  [DFN6-2X2-65-7P]  72.12 37.85 90 top
U45  AONR21357  [POWER-3X3-65-5P-ADNR21357]  94.27 14.2 0 bottom
U49  W25Q64FWZPIG  [WSON8-6X5-1_27-9P-W25Q64FWZPIG]  46.46 18.68 180 top
U93  IT5204FN/BX  [QFN32-4X4-4-33P-0_9H]  20.3 29.6 180 top
U124  UR0605B-FT021  [BGA78-GOOGLE-UR0605B]  55.48 17.41 0 top
U1001  MT8183V/A  [BGA599-MEDIA-MT8183-0_5S]  85.83 38.36 270 top
U1007  U69H025_21  [MODULE-16X12-108P-1_63H]  142.64 53.97 180 bottom
U2001  MT6358W/A  [BGA194-MEDIATEK-MT6358-0_5S]  106.82 38.65 0 top
U6404  *BMI160  [LGA14-3X2_5-5]  144.51 32.77 180 top
U6502  MAX98357AEWL+T  [BGA9-MAXIM-MAX98357A]  31.86 10.65 90 top
U6503  MAX98357AEWL+T  [BGA9-MAXIM-MAX98357A]  24.64 5.39 0 top
U6504  DA7219-02VBA  [BGA32-DIALOG-DA7219-02VBA]  11.67 30.99 0 top
U6514  TPS22930AYZVR  [BGA4-TEXAS-TPS22907YZTR]  32.62 32.14 0 top
U6517  STM32F098RCH6  [BGA64-ST-SMT32F098RC-0_5S]  125.59 50.17 90 top
U6522  TMUX1574RSVR  [QFN16-2_6X1_8-4-0_55H]  114.7 54.86 270 top
U6524  *INA3221AIRGVR  [QFN16-4X4-65-17P-MAX4063]  13.32 16.95 0 top
U6525  *INA3221AIRGVR  [QFN16-4X4-65-17P-MAX4063]  39.86 28.2 90 top
U6526  *INA3221AIRGVR  [QFN16-4X4-65-17P-MAX4063]  121.39 16.01 90 top
U6528  RT9740AGQW  [DFN14-3X2-4-11P-RT9740A]  129.65 17.91 0 top
U6530  *INA3221AIRGVR  [QFN16-4X4-65-17P-MAX4063]  52.66 42.68 90 top
U6531  TPS22930AYZVR  [BGA4-TEXAS-TPS22907YZTR]  62.59 13.09 0 top
U6533  FUSB302BUCX  [BGA9-FAIRCHILD-FUSB302B]  25.64 44.33 90 top
U6538  *INA219AIDCNR  [SOT23-8-2_8-65-8P]  130.01 59.95 180 bottom
U6539  *INA219AIDCNR  [SOT23-8-2_8-65-8P]  124.93 60.46 90 bottom
U6540  *INA219AIDCNR  [SOT23-8-2_8-65-8P]  120.35 32.26 90 bottom
U6541  *TS3A227EYFFR  [BGA16-TEXAS-TPS61280YFFR-0_5S]  11.16 25.28 90 top
U6546  GL852G-OHY60  [QFN28-5X5-5-29P-GL3213-OHY01]  68.44 28.07 270 top
U6547  M34E02-FMC6TG  [MLP8-3X2-5-9P]  121.22 60.51 180 top
U6548  SLG4E42757VTR  [QFN8-1_2X1-4]  49.64 18.17 90 bottom
U6552  RT9742GGJ5  [SOT23-5-2_794-9395-5P]  136.69 42.47 0 bottom
U6553  *RT9742CNGJ5  [SOT23-5-2_794-9395-5P]  44.05 10.55 180 top
U6554  *RT9742CNGJ5  [SOT23-5-2_794-9395-5P]  38.59 10.5 180 top
U6555  PI3USB9201ZTAEX  [QFN12-2X2-4]  20.81 43.44 0 top
U6558  *NX20P5090UK  [BGA15-NXP-NX20P5090UK]  31.43 43.44 90 top
U6559  IT8801BFN/CX  [QFN48-6X6-4-49P-IT8801]  140.7 15.88 0 top
U6563  *SN74AVC8T245RHLR  [QFN24-5_5X3_5-5-25P-SN74AVC8T245]  27.54 33.15 270 top
U6569  RT6214AHRGJ8F  [SOT23-2_8-65-8P-RT6218]  100.06 18.27 90 bottom
U6570  RT6256CGQUF  [QFN12-3X3-45-0_6H]  65.59 15.91 270 bottom
U6571  RT6256BGQUF  [QFN12-3X3-45-0_6H]  50.91 29.09 270 bottom
U6572  RT9742CGJ5  [SOT23-5-2_794-9395-5P]  42.15 44.2 0 top
U6573  RT9742CGJ5  [SOT23-5-2_794-9395-5P]  36.81 39.5 0 top
U6574  *ALS@TCS34003FN  [SENSOR-2_4X2-65-6P]  149.21 37.34 180 top
U6575  *ECO@BMM150  [BGA12-BOSCH-BMM150-0_5S-SMT]  148.19 43.9 90 top
U6576  *RT9742CGJ5  [SOT23-5-2_794-9395-5P]  16.7 11.41 180 top
U6577  *FPF2495UCX  [BGA9-FAIRCHILD-FPF2495UCX]  28.81 40.9 270 bottom
U6578  ANX7625BN-AC-R  [BGA64-ANALOGIX-ANX7625]  65.06 42.42 0 top
U6579  TPS22930AYZVR  [BGA4-TEXAS-TPS22907YZTR]  70.67 51.44 0 top
U6580  *GMR@HGDEDM013A  [SENSOR-1_3X0_9-5-4P]  128 68.2 180 top
U6581  TMP708AIDBVR  [SOT23-5-2_8-95-5P-G708]  71.41 43.34 270 bottom
U6582  TPD2S300YFFR  [BGA9-TEXAS-TPD2S300-0_5S]  23.86 41.28 180 bottom
UD1  H9HCNNNCPMALHR-NEE  [BGA200-HYNIX-H9HCNNN8RUMLHR]  85.53 51.89 0 top
VCN28_PMU  *TP  [TP2050]  110.9 36.71 90 top
VCN33_PMU  *TP  [TP2050]  116.11 41.37 90 top
VIBR_PMU  *TP  [TP2050]  114.61 45.78 90 top
VIO28_PMU  *TP  [TP2050]  112.02 38.34 180 bottom
VLDO28_PMU  *TP  [TP2050]  110.68 38 90 top
VMODEM  *TP  [TP2050]  104.61 44.23 0 top
X8101  26MHZ/10ppm  [XTL-2_5X2-1_7X1_3-1H]  110.57 30.95 0 top
Y1  27MHZ/10ppm  [XTL-3_2X2_5-2_2X1_7-0_8H]  18.91 16.31 270 top
Y2  12MHZ/20ppm  [XTL-2_5X2-1_85X1_55]  67.29 21.93 0 top
Y3  27MHZ/10ppm  [XTL-3_2X2_5-2_2X1_7-0_8H]  63.99 36.91 0 top

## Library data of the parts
BATT_DISABLE_ODL_MTK CHG_QONB_MTK EXT_PMIC_EN1 HUB_SDA HUB_TEST I2C1_SCL_MTK I2C1_SDA_MTK I2C6_SCL_MTK I2C6_SDA_MTK RTC32K_2V8 TP8273-TP8275 TP9080 TP9083 TP9084 TP9142 TP9143 TP9146 TP9149 TP9151 TP9152 TP9154 TP9155 TP9157-TP9163 TP9165-TP9170 TP9175-TP9183 = PAD_1
C1-C4 C6-C8 C10-C29 C44-C46 C141 C228 C229 C238-C240 C243 C246 C251 C333 C368 C375 C412 C414 C415 C426 C431 C434 C436-C440 C444 C447 C457 C487 C488 C491-C493 C495 C503 C504 C518 C526 C527 C533 C594 C748 C1811 C2001 C2002 C2004 C2007-C2011 C2013 C2016 C2023-C2032 C2101-C2103 C2105 C2106 C2108 C2112 C2113 C2116 C2117 C2120 C2121 C2124 C2125 C2129 C2130 C2132-C2134 C2136 C2138-C2142 C2144-C2149 C2302 C2303 C4407 C4408 C6101-C6106 C6209 C6221 C6324 C6329 C6401 C6404 C8001 C8101 C8201 C8202 C9016-C9019 C9035 C9036 C9061 C9063 C9066 C9067 C10350 C10354-C10359 C10365 C10367 C10368 C10370 C10372-C10374 C10379-C10396 C10399-C10402 C10412 C10413 C10420-C10428 C10430-C10437 C10444-C10449 C10451-C10458 C10460-C10462 C10468 C10472-C10475 C10478-C10486 C10488 C10489 C10491-C10496 C10499-C10505 C10508-C10510 C10525 C10533-C10535 C10538-C10540 C10550-C10552 C10566 C10570 C10571 C10575 C10576 C10604-C10606 C10610 C10613 C10614 C10620-C10624 C10627-C10647 C10649-C10653 C10656 C10660 C10662-C10668 C10670-C10710 C10712-C10718 PC18 PC131-PC140 = CAP_NON-POL_BGM
C175 C299 C10711 = CAP NON-POL_BGM
C749 = C_5
C1001 C1005 C1009-C1011 C1701-C1704 C1706 C1707 C1709 C1818 C1820 C1824 C1825 C1836-C1839 C4101 C4202 C4301 C4401 C4402 C4404 C4405 C4419 C5001 C5002 C7101 C7405-C7407 C9021 C9023 C10378 C10469 = C / 100 / nF / 0201
C1002-C1004 C1006 C1502 C1503 C1808 C1810 C1812-C1817 C1819 C1821-C1823 C1826-C1835 C1840-C1843 C2135 C4004-C4007 C4011-C4014 C4203 C4302 C4409-C4418 C4420-C4426 C6229 C6230 C6701 C6702 C6901 C7102 C7104 C7210 C9047-C9058 C10438-C10440 C10442 C10443 = C / 1 / uF / 0201
C2003 C4427 = C / 22 / uF / 0603
C2005 C2021 = C / 10 / uF / 0603
C2111 C4403 C9020 C9022 = C / 4.7 / uF / 0402
C4406 C10619 = C / 2.2 / uF / 0402
CLIP9-CLIP12 CLIP17 CLIP19-CLIP21 = CLIP_3P_BGM
CON12 = CON12X1_2
CON15 = HEADER 5_0
CON16 = HOUSING_50P_2R_BGM
CON6201 = COMBOJACK_7P_BGM
CON7101 = USB3_TYPE_C_0
CON7102 CON9105 = FFCFPC_30P_BGM
CON9104 = CON_SPK_2
D1 D2740 D2742 D2743 = TVS_DIODE_UNI_BGM
D7 = LED_4P_ROYG_BGM_1
D761 = BAT54C_BGM
D2705-D2708 D2736-D2739 = Schottky_DIODE_BGM
D2711-D2734 ESD7102 = TVS_DIODE_BGM
D2741 = PESD5V0X2UM_BGM
EMI7101 = EMI / DLP11RN450UL2
ESD6204 ESD6206 ESD7507-ESD7509 = ESD / DF2B6.8M1ACT
ESD6309 ESD6310 ESD7505 ESD7506 = ESD / AZ4212-01F.R7GR
ESD7502 = ESD / ESD5451NKM
ESD7511 = ESD / AZ4514-01F
F2 = FUSE
FB1-FB5 = FerritBead
HOLE7-HOLE20 = 3x2_6.1
J15 = FFCFPC_40P_BGM
J17 = FFCFPC_20P_BGM
J20 J24 = Housing_6P_BGM
L12 = BW_BGM
L16 PL2001-PL2003 PL2006-PL2009 = INDUCTOR_V01_BGM
L48 = INDUCTOR_V02_BGM
L6904 = BEAD_BGM
NC63 NC245-NC252 NC255 NC256 NC266-NC275 NC279-NC284 NC287 NC288 NC291-NC296 NC302 NC303 = NC PAD 1206 SMD_0
NTC1501 NTC1502 = Thermistor_BGM
PL2702-PL2704 = INDUCTOR_BGM
PP1800_ALW_PG PP3300_ALW_PG PP5000_ALW_PG1 VCN28_PMU VCN33_PMU VIBR_PMU VIO28_PMU VLDO28_PMU VMODEM = TEST POINT DIP0_1.6
PQ1 PQ2 = MOS-N-Dual_9P_BGM
PR23 PR158 PR263 PR264 R20 R174 R217 R219 R405 R420 R503 R504 R521 R537 R538 R619 R707 R720 R721 R940-R942 R1105 R1106 R1109 R1110 R1113 R1114 R1501 R1502 R9499 R9572 R90267 R90460-R90462 R90473 R90505-R90509 R90605 R90666 R90671 R90673 R90677 R90726 R90728 R90732 R90740 R90741 R90792 R90813 R90814 R90816 R90818 R90820-R90842 R90853-R90855 R90937 R90976 R90982 R90983 R90987 R91029 R91051 R91052 R91057 R91063 R91087 R91089 R91112 R91115 R91116 R91145 R91148 R91150-R91152 R91156-R91159 R91161-R91163 R91169 R91171 R91182 R91184 R91185 R91188 R91189 R91191 R91192 R91196 R91199 R91210 R91211 R91226 R91233 R91238 R91240-R91244 R91246-R91249 R91252-R91254 R91265-R91267 R91269-R91271 R91273 R91274 R91276 R91279 R91282 R91293-R91295 R91298 R91302-R91308 R91310 R91314 R91316 R91320-R91323 R91326-R91329 = RES_BGM
PU1 = RT9078-18GJ5_5P_BGM
Q2 Q55 Q705 Q706 Q718 Q723-Q727 Q748 Q757 Q759 Q780-Q788 Q790-Q795 Q797 Q798 Q802 Q803 = MOS-N_3P_ESD_BGM
Q3 Q4 Q80 Q81 Q739 Q776-Q779 Q799 Q800 = 2N7002DW
Q8 Q717 = PMZB670UPE_BGM
Q730-Q732 Q734 Q762 Q763 Q766-Q768 Q806-Q808 = MOS-N_3P_ESD_123_1_BGM
Q750 = MOS_P_PMZ350UPE_3P_BGM
Q789 Q801 U45 = MOS-P_8P_BGM
Q804 Q805 = MOS-P_3P_ESD_BGM
R1-R4 R17 R252 R293 R313 R314 R323 R334 R350 R442 R443 R2001 R2204-R2206 R2301-R2304 R3001-R3006 R6206 R6207 R6209 R6210 R8201 R90154 R90155 R90268 R90336-R90343 R90374-R90377 R90380 R90382-R90388 R90407 R90409 R90410 R90415-R90418 R90423-R90434 R90441 R90448-R90453 R90455 R90457 R90472 R90481-R90484 R90488-R90504 R90514 R90515 R90521-R90524 R90535 R90539-R90544 R90560 R90562 R90563 R90568 R90569 R90580-R90582 R90587 R90591 R90597 R90610-R90612 R90614 R90624 R90627 R90629 R90630 R90640 R90656 R90683 R90696-R90701 R90715-R90720 R90725 R90727 R90729 R90738 R90742-R90746 R90751 R90753 R90757 R90810 R90811 R90843 R90856-R90861 R90870 R90897-R90901 R90906 R90913 R90952 R90953 R90962 R90963 R90973-R90975 R90986 R90988 R90991-R90993 R90995 R91008 R91009 R91013 R91028 R91032 R91061 R91062 R91064 R91066 R91079-R91082 R91088 R91091-R91094 R91097-R91099 R91113 R91121 R91126 R91127 R91129-R91135 R91137 R91142-R91144 R91146 R91170 R91183 R91186 R91190 R91202-R91207 R91212-R91214 R91217-R91225 R91231 R91232 R91239 R91245 R91250 R91251 R91255-R91258 R91260 R91261 R91275 R91277 R91278 R91281 R91283-R91290 R91296 R91297 R91299 R91309 R91311-R91313 R91315 R91317-R91319 R91324 R91325 R91330 R91331 = RES_BGM_0
R10 R12 R13 R102 R184 R185 R187-R194 R215 R218 R277 R330-R332 R338 R391 R476 R512 R709 R7701 R8001 R90163 R90164 R90264 R90348 R90352 R90354 R90364 R90366 R90368 R90371 R90373 R90389 R90435 R90438-R90440 R90442 R90465 R90474 R90475 R90479 R90512 R90518-R90520 R90525 R90530 R90537 R90538 R90554 R90558 R90603 R90604 R90606 R90622 R90628 R90633 R90638 R90639 R90641-R90655 R90658 R90659 R90662 R90667-R90669 R90672 R90674 R90675 R90678 R90680-R90682 R90688 R90695 R90708 R90735 R90758 R90783 R90784 R90815 R90819 R90844 R90845 R90852 R90868 R90874 R90876 R90877 R90892 R90893 R90904 R90912 R90914-R90917 R90941 R90966 R90967 R90969 R90984 R90985 R91031 R91100 R91111 R91117 R91118 R91125 R91136 R91139 R91147 R91160 R91172-R91175 R91179 R91181 R91187 R91194 R91195 R91200 R91209 R91228-R91230 R91234-R91237 R91259 R91268 R91280 R91291 R91292 R91300 R91301 = SHORTPAD_V01_BGM
R15 R1101 R1102 R1107 R1108 R1111 R1112 R90332 R90871 R90872 = R / 4.7 / K / 0201
R612 R654 = R_Current_SEN_BGM
R1001 R1004 R1007 R1009-R1012 R1103 R1104 = R / 10 / K / 0201
R4001 = R / 60.4 / ohm / 0201
R4404 R4405 R4407 = R / 240 / ohm / 0201
R6225 R90266 R90333-R90335 R90365 R90367 R90707 R90737 R90759-R90765 R90773 R90774 R90776-R90782 R91140 = R / 0 / ohm / 0603
R90265 R90706 = R / 0 / ohm / 0402
R90463 R90471 R90561 R90692 = R / 2.2 / K / 0201
R90527-R90529 R91141 = R / 0 / ohm / 0201
R90625 R90626 = R / 100 / K / 0201
SH1701 SH1801-SH1808 SH2001-SH2003 SH2006 SH2008 SH2010-SH2013 SH2015 SH2101 SH2140 SH2144 SH2302 SH4401 SH4402 SH6101 SH6102 SH6204 SH8101 SH8102 = SHORT / 4MIL
SW7504 = SW_4P_1324_BGM
TP109 TP110 TP212 TP213 TP230 TP231 TP9044 TP9055 TP9060 TP9061 TP9064 TP9065 TP9067-TP9075 TP9079 TP9141 TP9184 = TP_BGM
TP9066 = TP_BGM_1
U1 = IT6505FN/BX_88P_BGM
U2 U3 = AZ1045-04F_BGM
U5 = SN74AVC16T245ZQLR_56P_BGM
U6 = ISL9238HRTZ-T_BGM_2
U12 = LM393_0
U18 = EMMC_153P_BGM_1
U23 = RT5710AHGQW_6P_BGM
U49 = W25Q32DW_0
U93 = IT5204FN/BX_32P_BGM
U124 = H1
U1001 = MT8183V/A_599P_BGM
U1007 = U69H025_21_108P_BGM
U2001 = MT6358W/A_194P_BGM
U6404 = BMI160_2
U6502 U6503 = MAX98357A
U6504 = DA7219
U6514 U6531 U6579 = TPS22930AYZVR_4P_BGM
U6517 = STM32F098RCH6
U6522 = TMUX1574RSVR_16P_BGM
U6524-U6526 U6530 = INA3221AIRGVR_BGM_3
U6528 = RT9740AGQW_14P_BGM_5
U6533 = FUSB302BUCX_BGM
U6538-U6540 = INA219AIDCNR_8P_BGM
U6541 = TS3A227EYFFR
U6546 = GL852G-OHG12_BGM
U6547 = M34E04-FMC9TG_BGM_0
U6548 = SLG4E42757VTR_V1_8P_BGM
U6552 = r1172x_0
U6553 U6554 = RT9742CNGJ5_5P_BGM
U6555 = PI3USB9201ZTAEX_12P_V1_BGM
U6558 = NX20P5090UK_BGM
U6559 = IT8801AFN/CX_48P_V2_BGM
U6563 = SN74AVC8T245RHLR_24P_BGM
U6569 = RT6214AHRGJ8F
U6570 = RT6256CGQUF_12P_BGM_0
U6571 = RT6256BGQUF_12P_BGM_1
U6572 U6573 U6576 = RT9742QGJ5_5P_BGM
U6574 = TCS34003FN_6P_BGM
U6575 = BMM150_BGM
U6577 = FPF2495UCX_BGM
U6578 = ANX7625BN-AC-R_64P_BGM
U6580 = ME268-002_0
U6581 = LM86_1
U6582 = TPD2S300YFFR_9P_BGM
UD1 = LPDDR4
X8101 = CRYSTAL_EXS00A-CS11019_4P_BGM
Y1-Y3 = CRYSTAL_4P_BGM

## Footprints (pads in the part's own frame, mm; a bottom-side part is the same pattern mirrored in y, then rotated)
2D-BARCODE-8X8-S
  round 0.991 smd: 1(7,-4)
50208-00601-V02-6P-L
  rect 0.508x0.991 smd: 1(-2,1.95) 2(-1.2,1.95) 3(-0.4,1.95) 4(0.4,1.95) 5(1.2,1.95) 6(2,1.95)
  rect 1.194x1.702 smd: 7(-3.3,0) 8(3.3,0)
50278-00401-001-4P-L
  rect 0.787x1.905 smd: 1(-1.875,4.925) 2(-0.625,4.925) 3(0.625,4.925) 4(1.875,4.925)
  rect 1.295x3.353 smd: 5(-4.725,0) 6(4.725,0)
50696-0200M-V02-20P-L
  rect 0.305x0.787 smd: 1(-4.75,2.5) 2(-4.25,2.5) 3(-3.75,2.5) 4(-3.25,2.5) 5(-2.75,2.5) 6(-2.25,2.5) 7(-1.75,2.5) 8(-1.25,2.5) 9(-0.75,2.5) 10(-0.25,2.5) 11(0.25,2.5) 12(0.75,2.5) 13(1.25,2.5) 14(1.75,2.5) 15(2.25,2.5) 16(2.75,2.5) 17(3.25,2.5) 18(3.75,2.5) 19(4.25,2.5) 20(4.75,2.5)
  rect 0.406x0.787 smd: 21(-5.75,0) 22(5.75,0)
51693-04001-V01-40P-L
  rect 0.305x1.295 smd: 1(-9.75,5.65) 2(-9.25,5.65) 3(-8.75,5.65) 4(-8.25,5.65) 5(-7.75,5.65) 6(-7.25,5.65) 7(-6.75,5.65) 8(-6.25,5.65) 9(-5.75,5.65) 10(-5.25,5.65) 11(-4.75,5.65) 12(-4.25,5.65) 13(-3.75,5.65) 14(-3.25,5.65) 15(-2.75,5.65) 16(-2.25,5.65) 17(-1.75,5.65) 18(-1.25,5.65) 19(-0.75,5.65) 20(-0.25,5.65) 21(0.25,5.65) 22(0.75,5.65) 23(1.25,5.65) 24(1.75,5.65) 25(2.25,5.65) 26(2.75,5.65) 27(3.25,5.65) 28(3.75,5.65) 29(4.25,5.65) 30(4.75,5.65) 31(5.25,5.65) 32(5.75,5.65) 33(6.25,5.65) 34(6.75,5.65) 35(7.25,5.65) 36(7.75,5.65) 37(8.25,5.65) 38(8.75,5.65) 39(9.25,5.65) 40(9.75,5.65)
  rect 1.803x2.21 smd: 41(-11.9,0) 42(11.9,0)
AUDIO-2SJ3080-108111F-6P
  oval 0.991x1.803 hole 0.61x1.397: 1(-4.85,7.225) 2(4.7,1.725) 3(-4.85,-0.575) 4(4.7,-1.175) 5(4.7,7.225) 6(4.7,4.475) 7(-4.85,3.125)
AXK750147G-50P-LDV
  rect 0.406x1.092 smd: 1(-4.885,-2.3) 2(-4.885,2.3) 49(4.885,-2.3) 50(4.885,2.3)
  rect 0.203x1.092 smd: 3(-4.4,-2.3) 4(-4.4,2.3) 5(-4,-2.3) 6(-4,2.3) 7(-3.6,-2.3) 8(-3.6,2.3) 9(-3.2,-2.3) 10(-3.2,2.3) 11(-2.8,-2.3) 12(-2.8,2.3) 13(-2.4,-2.3) 14(-2.4,2.3) 15(-2,-2.3) 16(-2,2.3) 17(-1.6,-2.3) 18(-1.6,2.3) 19(-1.2,-2.3) 20(-1.2,2.3) 21(-0.8,-2.3) 22(-0.8,2.3) 23(-0.4,-2.3) 24(-0.4,2.3) 25(0,-2.3) 26(0,2.3) 27(0.4,-2.3) 28(0.4,2.3) 29(0.8,-2.3) 30(0.8,2.3) 31(1.2,-2.3) 32(1.2,2.3) 33(1.6,-2.3) 34(1.6,2.3) 35(2,-2.3) 36(2,2.3) 37(2.4,-2.3) 38(2.4,2.3) 39(2.8,-2.3) 40(2.8,2.3) 41(3.2,-2.3) 42(3.2,2.3) 43(3.6,-2.3) 44(3.6,2.3) 45(4,-2.3) 46(4,2.3) 47(4.4,-2.3) 48(4.4,2.3)
BGA4-TEXAS-TPS22907YZTR
  round 0.254 smd: A1(-0.25,-0.25) A2(-0.25,0.25) B1(0.25,-0.25) B2(0.25,0.25)
BGA9-FAIRCHILD-FPF2495UCX
  round 0.203 smd: A1(-0.4,-0.4) A2(-0.4,0) A3(-0.4,0.4) B1(0,-0.4) B2(0,0) B3(0,0.4) C1(0.4,-0.4) C2(0.4,0) C3(0.4,0.4)
BGA9-FAIRCHILD-FUSB302B
  round 0.254 smd: A1(-0.4,-0.4) A2(-0.4,0) A3(-0.4,0.4) B1(0,-0.4) B2(0,0) B3(0,0.4) C1(0.4,-0.4) C2(0.4,0) C3(0.4,0.4)
BGA9-MAXIM-MAX98357A
  round 0.254 smd: A1(-0.4,-0.4) A2(-0.4,0) A3(-0.4,0.4) B1(0,-0.4) B2(0,0) B3(0,0.4) C1(0.4,-0.4) C2(0.4,0) C3(0.4,0.4)
BGA9-TEXAS-TPD2S300-0_5S
  round 0.254 smd: A1(-0.4,-0.4) A2(-0.4,0) A3(-0.4,0.4) B1(0,-0.4) B2(0,0) B3(0,0.4) C1(0.4,-0.4) C2(0.4,0) C3(0.4,0.4)
BGA12-BOSCH-BMM150-0_5S-SMT
  round 0.254 smd: A1(-0.601,-0.601) A3(-0.601,-0.035) A5(-0.601,0.531) B2(-0.318,-0.318) B4(-0.318,0.248) C1(-0.035,-0.601) C5(-0.035,0.531) D2(0.248,-0.318) D4(0.248,0.248) E1(0.531,-0.601) E3(0.531,-0.035) E5(0.531,0.531)
BGA15-NXP-NX20P5090UK
  round 0.254 smd: A1(-0.5,-1) A2(0,-1) A3(0.5,-1) B1(-0.5,-0.5) B2(0,-0.5) B3(0.5,-0.5) C1(-0.5,0) C2(0,0) C3(0.5,0) D1(-0.5,0.5) D2(0,0.5) D3(0.5,0.5) E1(-0.5,1) E2(0,1) E3(0.5,1)
BGA16-TEXAS-TPS61280YFFR-0_5S
  round 0.254 smd: A1(-0.6,-0.6) A2(-0.6,-0.2) A3(-0.6,0.2) A4(-0.6,0.6) B1(-0.2,-0.6) B2(-0.2,-0.2) B3(-0.2,0.2) B4(-0.2,0.6) C1(0.2,-0.6) C2(0.2,-0.2) C3(0.2,0.2) C4(0.2,0.6) D1(0.6,-0.6) D2(0.6,-0.2) D3(0.6,0.2) D4(0.6,0.6)
